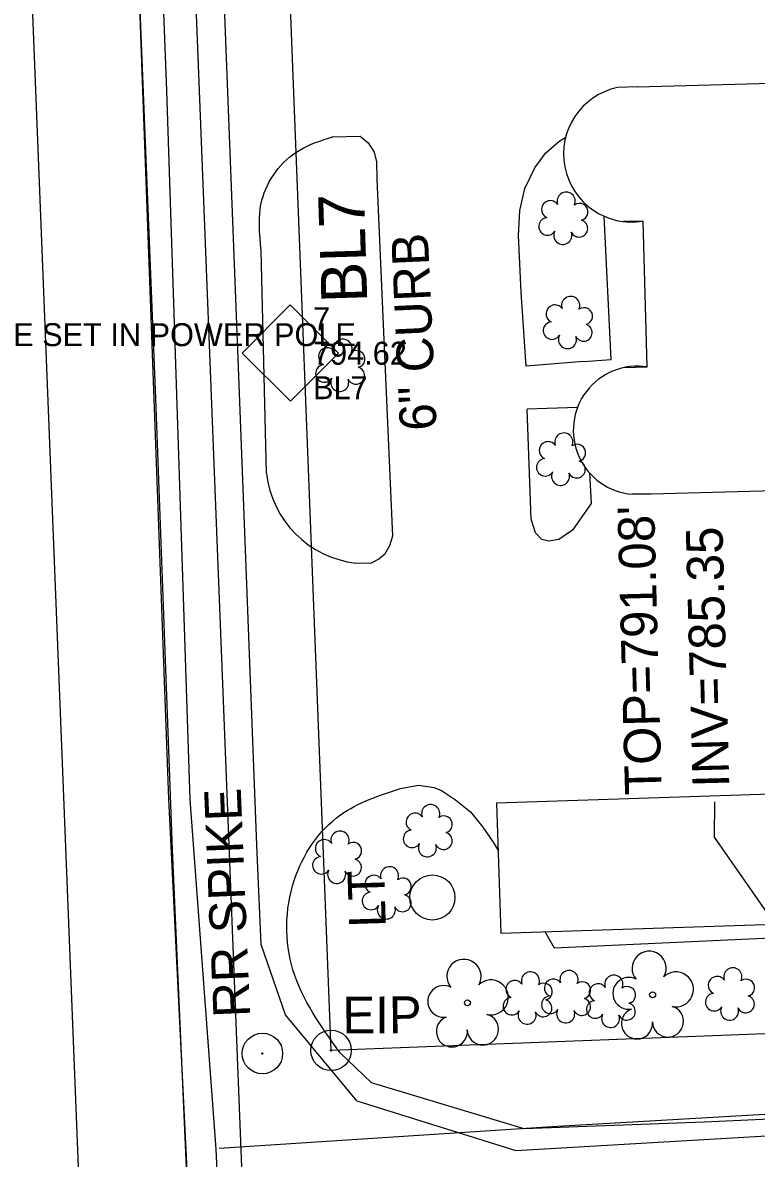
# Model space of a CAD drawing. Extents: x 1627482 to 1629573, y 760826 to 766301.
# Drawn here: x 1628380.2 to 1628460.1, y 763876.2 to 763999.8 of the extents above; entities that cross this region are included whole.
import ezdxf

# ---------------------------------------------------------------- set-up
doc = ezdxf.new("R2010")
doc.units = 0
for name, color, linetype in [('CTL Secondary Horizontal and Vertical CELL', 7, 'Continuous'), ('CTL Secondary Horizontal and Vertical Cogo Comment', 7, 'Continuous'), ('CTL Secondary Horizontal and Vertical Cogo Elevation', 7, 'Continuous'), ('CTL Secondary Horizontal and Vertical Cogo Number', 7, 'Continuous'), ('CTL Secondary Horizontal and Vertical Text', 7, 'Continuous'), ('CTL Vertical Benchmark Cogo Comment', 7, 'Continuous'), ('Exist Building', 7, 'Continuous'), ('Exist Building Metal Canopy', 7, 'Continuous'), ('Exist Horizontal Alignment', 7, 'Continuous'), ('Exist Other Culture Area Outline', 7, 'Continuous'), ('Exist Property Iron Pin CELL', 7, 'Continuous'), ('Exist Property Iron Pin Text', 7, 'Continuous'), ('Exist Right of Way Line', 7, 'Continuous'), ('Exist Roads Curbs', 7, 'Continuous'), ('Exist Roads Curbs Text', 7, 'Continuous'), ('Exist Roads EOP', 7, 'Continuous'), ('Exist Roads EOT', 7, 'Continuous'), ('Exist Utilities Gas UG Line SUE LOS B', 7, 'Continuous'), ('Exist Utilities Other Pole CELL', 7, 'Continuous'), ('Exist Utilities Other Pole Text', 7, 'Continuous'), ('Exist Utilities Sanitary Sewer Manhole Text', 7, 'Continuous'), ('Exist Utilities Sanitary Sewer UG Line', 7, 'Continuous'), ('Exist Utilities Sanitary Sewer UG Line Invert Elevation', 7, 'Continuous'), ('Exist Utilities Sanitary Sewer UG Line Leader', 7, 'Continuous'), ('Exist Utilities Water UG Line SUE LOS B', 7, 'Continuous'), ('Exist Vegetation Shrub CELL', 7, 'Continuous'), ('Exist Vegetation Tree CELL', 7, 'Continuous')]:
    doc.layers.add(name, color=color, linetype=linetype)

# ---------------------------------------------------------------- blocks, each defined once
blk = doc.blocks.new('EXIST PROPERTY IRON PIN_368')
at = {"layer": 'Exist Property Iron Pin CELL'}
for radius in [3.36, 0.108]:
    blk.add_circle((0, 0), radius, dxfattribs=at)

msp = doc.modelspace()

# ---------------------------------------------------------------- linework, layer by layer
at = {"layer": 'CTL Secondary Horizontal and Vertical CELL'}
msp.add_line((1628409.34, 763963.83), (1628409.34, 763963.83), dxfattribs=at)
msp.add_lwpolyline([(1628404.13, 763963.85), (1628409.37, 763969.09), (1628414.62, 763963.84), (1628409.38, 763958.6)], close=True, dxfattribs=at)
at = {"layer": 'Exist Building'}
for p, q in [((1628447.21, 763992.84), (1628445, 763992.75)), ((1628448.23, 763962.34), (1628447.8, 763978.22)), ((1628441.31, 763962.93), (1628435.07, 763962.43)), ((1628440.66, 763957.94), (1628435.17, 763957.75))]:
    msp.add_line(p, q, dxfattribs=at)
for points in [[(1628447.19, 763992.84), (1628447.21, 763992.84), (1628492.18, 763994.07), (1628492.4, 763985.86), (1628538.86, 763987.12), (1628539.46, 763965.07), (1628527.45, 763964.75), (1628527.83, 763950.63), (1628448.67, 763948.48), (1628446.6, 763948.49)], [(1628447.8, 763978.22), (1628445.68, 763978.17)], [(1628445.76, 763962.27), (1628448.23, 763962.34)]]:
    msp.add_lwpolyline(points, dxfattribs=at)
for centre, radius, start, end in [((1628446.54, 763985.51), 7.4, 102.04, 279.7685), ((1628447.18, 763955.44), 6.98, 81.3515, 265.2404)]:
    msp.add_arc(centre, radius, start, end, dxfattribs=at)
at = {"layer": 'Exist Building Metal Canopy'}
msp.add_lwpolyline([(1628555.82, 763918.91), (1628431.84, 763914.86), (1628432.31, 763900.72), (1628556.29, 763904.77)], close=True, dxfattribs=at)
at = {"layer": 'Exist Horizontal Alignment'}
msp.add_line((1628461.18, 761975.88), (1628351.56, 764755.6), dxfattribs=at)
at = {"layer": 'Exist Other Culture Area Outline'}
msp.add_lwpolyline([(1628441.31, 763962.93), (1628444.32, 763963.14), (1628443.57, 763978.74)], dxfattribs=at)
at = {"layer": 'Exist Right of Way Line'}
msp.add_lwpolyline([(1628629.23, 763896.22), (1628413.81, 763887.95), (1628407.97, 764037.8)], dxfattribs=at)
at = {"layer": 'Exist Roads Curbs'}
for p, q in [((1628414.01, 763987.37), (1628413.96, 763987.4)), ((1628406.78, 763950.74), (1628406.2, 763975.01)), ((1628416.5, 763940.98), (1628416.51, 763940.98)), ((1628421.35, 763916.45), (1628421.38, 763916.44)), ((1628431.48, 763910.62), (1628432.01, 763909.69)), ((1628437.08, 763900.88), (1628438.1, 763899.1)), ((1628414.79, 763887.7), (1628414.79, 763887.7))]:
    msp.add_line(p, q, dxfattribs=at)
for points in [[(1628414.01, 763987.37), (1628416.98, 763987.46), (1628417.84, 763986.72), (1628418.51, 763985.7), (1628418.77, 763984.66), (1628418.78, 763982.76), (1628419.57, 763965.3), (1628420.5, 763943.92), (1628420.19, 763942.88), (1628419.62, 763941.94), (1628419, 763941.4), (1628418.1, 763940.94), (1628416.51, 763940.98)], [(1628435.07, 763962.43), (1628434.51, 763970.46), (1628434.24, 763976.66), (1628434.37, 763979.35), (1628434.91, 763981.76), (1628435.99, 763984), (1628437.16, 763985.61), (1628438.64, 763986.88), (1628439.38, 763987.36)], [(1628441.96, 763950.81), (1628442.16, 763947.49), (1628440.12, 763944.57), (1628438.63, 763943.56), (1628437.53, 763943.37), (1628436.77, 763943.55), (1628436.08, 763944.27), (1628435.6, 763945.77), (1628435.17, 763957.75)], [(1628421.38, 763916.44), (1628423.33, 763916.81), (1628425.03, 763916.57), (1628425.83, 763916.24), (1628427.36, 763915.21), (1628429, 763913.93), (1628430.34, 763912.24), (1628431.48, 763910.62)], [(1628438.1, 763899.1), (1628498.67, 763901.9), (1628545.14, 763903.55)], [(1628552.59, 763884.54), (1628527.87, 763883.37), (1628490.27, 763881.77), (1628454.44, 763880.15), (1628434.85, 763879.42), (1628418.21, 763884.4), (1628414.79, 763887.7)]]:
    msp.add_lwpolyline(points, dxfattribs=at)
msp.add_ellipse((1628417.74, 763951.95), major_axis=(6.43, -8.97), ratio=0.998624, start_param=4.200206, end_param=5.548948, dxfattribs=at)
for points in [[(1628406.2, 763975.01), (1628406.28, 763980.49), (1628410.33, 763985.91), (1628414.01, 763987.37)], [(1628414.79, 763887.7), (1628409.66, 763896.72), (1628409.79, 763906.45), (1628414.84, 763913.58), (1628421.35, 763916.45)]]:
    msp.add_spline(points, degree=3, dxfattribs=at)
at = {"layer": 'Exist Roads EOP'}
for q in [(1628408.84, 763891.81), (1628433.94, 763877.05)]:
    msp.add_line((1628416.6, 763882.46), q, dxfattribs=at)
for points in [[(1628408.84, 763891.81), (1628406.21, 763899.46), (1628405.73, 763910.27), (1628403.83, 763959.47), (1628401.88, 764010.06), (1628400.01, 764060.11), (1628398.02, 764110.14), (1628396.15, 764159.43), (1628394.21, 764209.26), (1628392.32, 764258.48), (1628390.36, 764308.46), (1628388.47, 764357.87), (1628386.62, 764407.25), (1628384.64, 764457.21), (1628382.85, 764505.87)], [(1628416.6, 763882.46), (1628433.94, 763877.05), (1628552.51, 763883.97)]]:
    msp.add_lwpolyline(points, dxfattribs=at)
at = {"layer": 'Exist Roads EOT'}
msp.add_lwpolyline([(1628372.75, 764529.41), (1628373.69, 764505.24), (1628375.41, 764455.77), (1628377.18, 764406.72), (1628379.24, 764357.37), (1628381.34, 764307.42), (1628382.92, 764258.08), (1628384.96, 764208.76), (1628386.88, 764159.37), (1628389.04, 764109.02), (1628390.75, 764059.72), (1628392.64, 764009.33), (1628394.69, 763958.92), (1628396.48, 763909.8), (1628398.7, 763859.53)], dxfattribs=at)
at = {"layer": 'Exist Utilities Gas UG Line SUE LOS B'}
for points in [[(1628413.99, 763549.83), (1628410.61, 763659.76), (1628406.72, 763757.73), (1628401.3, 763877.18), (1628398.45, 763915.27), (1628395.93, 763992.39), (1628393.09, 764066.3), (1628389.92, 764168.16), (1628388.3, 764264.41), (1628388.86, 764316.24), (1628388.66, 764366.29), (1628385.61, 764456.2), (1628379.32, 764518.2), (1628376.01, 764570.05), (1628373.69, 764583.54), (1628373.66, 764583.52), (1628369.04, 764671.92), (1628368.81, 764733.47), (1628365.47, 764801.3), (1628365.41, 764842.67), (1628323.45, 764841.73)], [(1628401.62, 763877.31), (1628437.85, 763879.67), (1628499.31, 763883.23), (1628538.09, 763884.2), (1628595.67, 763885.75)]]:
    msp.add_lwpolyline(points, dxfattribs=at)
at = {"layer": 'Exist Utilities Other Pole CELL'}
msp.add_circle((1628424.85, 763904.59), 2.46, dxfattribs=at)
at = {"layer": 'Exist Utilities Sanitary Sewer UG Line'}
msp.add_line((1628404.33, 763869.48), (1628385.46, 764348.07), dxfattribs=at)
at = {"layer": 'Exist Utilities Sanitary Sewer UG Line Leader'}
msp.add_lwpolyline([(1628483.37, 763871.36), (1628455.59, 763911.15), (1628455.61, 763915.02)], dxfattribs=at)
at = {"layer": 'Exist Utilities Water UG Line SUE LOS B'}
msp.add_lwpolyline([(1628407.24, 763655.16), (1628402.4, 763754.94), (1628399.06, 763856.51), (1628396.12, 763915.33), (1628393.3, 763992.46), (1628390.7, 764066.34), (1628386.72, 764168.39), (1628382.56, 764256.29), (1628378.23, 764373.67), (1628375.54, 764455.63), (1628372.03, 764542.25), (1628370.17, 764583.36), (1628366.9, 764671.42), (1628365.27, 764739.23), (1628362.16, 764808.05), (1628361.5, 764823.25), (1628356.13, 764896.21), (1628352.11, 764986.77), (1628341.94, 765081.92), (1628331.48, 765195.63), (1628321.82, 765290.23), (1628312.98, 765379.55), (1628303.79, 765478.36)], dxfattribs=at)
at = {"layer": 'Exist Vegetation Shrub CELL'}
for p, q in [((1628439.19, 763978.34), (1628439.19, 763978.34)), ((1628439.68, 763966.99), (1628439.68, 763966.99)), ((1628414.88, 763962.33), (1628414.88, 763962.33)), ((1628438.94, 763952.12), (1628438.94, 763952.12)), ((1628424.43, 763911.68), (1628424.43, 763911.68)), ((1628414.55, 763908.79), (1628414.55, 763908.79)), ((1628419.96, 763904.91), (1628419.96, 763904.91)), ((1628435.3, 763893.47), (1628435.3, 763893.47)), ((1628439.5, 763893.62), (1628439.5, 763893.62)), ((1628444.39, 763893.11), (1628444.39, 763893.11)), ((1628457.36, 763893.91), (1628457.36, 763893.91))]:
    msp.add_line(p, q, dxfattribs=at)
for centre, radius, start, end in [((1628439.42, 763980.38), 0.99, 334.8391, 200.4717), ((1628437.71, 763979.47), 0.968, 35.8908, 245.4216), ((1628440.86, 763979.21), 0.929, 284.4567, 126.0861), ((1628437.39, 763977.63), 0.955, 95.1099, 327.9534), ((1628440.83, 763977.41), 0.937, 204.9913, 73.4601), ((1628439.06, 763976.65), 0.984, 151.2797, 21.387), ((1628439.91, 763969.03), 0.99, 334.8391, 200.4717), ((1628438.2, 763968.12), 0.968, 35.8908, 245.4216), ((1628441.36, 763967.86), 0.929, 284.4567, 126.0861), ((1628437.88, 763966.29), 0.955, 95.1099, 327.9534), ((1628441.32, 763966.07), 0.937, 204.9913, 73.4601), ((1628415.11, 763964.37), 0.99, 334.8391, 200.4717), ((1628439.56, 763965.31), 0.984, 151.2797, 21.387), ((1628413.4, 763963.46), 0.968, 35.8908, 245.4216), ((1628416.56, 763963.2), 0.929, 284.4567, 126.0861), ((1628413.08, 763961.63), 0.955, 95.1099, 327.9534), ((1628416.52, 763961.4), 0.937, 204.9913, 73.4601), ((1628414.75, 763960.65), 0.984, 151.2797, 21.387), ((1628439.17, 763954.16), 0.99, 334.8391, 200.4717), ((1628437.45, 763953.24), 0.968, 35.8908, 245.4216), ((1628440.61, 763952.99), 0.929, 284.4567, 126.0861), ((1628437.14, 763951.41), 0.955, 95.1099, 327.9534), ((1628440.57, 763951.19), 0.937, 204.9913, 73.4601), ((1628438.81, 763950.43), 0.984, 151.2797, 21.387), ((1628424.66, 763913.72), 0.99, 334.8391, 200.4717), ((1628422.95, 763912.81), 0.968, 35.8908, 245.4216), ((1628426.1, 763912.55), 0.929, 284.4567, 126.0861), ((1628414.78, 763910.83), 0.99, 334.8391, 200.4717), ((1628422.63, 763910.97), 0.955, 95.1099, 327.9534), ((1628426.07, 763910.75), 0.937, 204.9913, 73.4601), ((1628413.06, 763909.92), 0.968, 35.8908, 245.4216), ((1628416.22, 763909.66), 0.929, 284.4567, 126.0861), ((1628424.3, 763910), 0.984, 151.2797, 21.387), ((1628412.75, 763908.09), 0.955, 95.1099, 327.9534), ((1628416.18, 763907.86), 0.937, 204.9913, 73.4601), ((1628420.18, 763906.95), 0.99, 334.8391, 200.4717), ((1628414.42, 763907.11), 0.984, 151.2797, 21.387), ((1628418.47, 763906.04), 0.968, 35.8908, 245.4216), ((1628421.63, 763905.78), 0.929, 284.4567, 126.0861), ((1628418.15, 763904.21), 0.955, 95.1099, 327.9534), ((1628421.59, 763903.98), 0.937, 204.9913, 73.4601), ((1628419.83, 763903.23), 0.984, 151.2797, 21.387), ((1628457.58, 763895.95), 0.99, 334.8391, 200.4717), ((1628433.81, 763894.59), 0.968, 35.8908, 245.4216), ((1628435.53, 763895.51), 0.99, 334.8391, 200.4717), ((1628438.02, 763894.75), 0.968, 35.8908, 245.4216), ((1628439.73, 763895.66), 0.99, 334.8391, 200.4717), ((1628444.61, 763895.15), 0.99, 334.8391, 200.4717), ((1628455.87, 763895.03), 0.968, 35.8908, 245.4216), ((1628459.03, 763894.77), 0.929, 284.4567, 126.0861), ((1628436.97, 763894.34), 0.929, 284.4567, 126.0861), ((1628441.17, 763894.49), 0.929, 284.4567, 126.0861), ((1628442.9, 763894.23), 0.968, 35.8908, 245.4216), ((1628446.06, 763893.98), 0.929, 284.4567, 126.0861), ((1628433.5, 763892.76), 0.955, 95.1099, 327.9534), ((1628436.93, 763892.54), 0.937, 204.9913, 73.4601), ((1628437.7, 763892.91), 0.955, 95.1099, 327.9534), ((1628441.14, 763892.69), 0.937, 204.9913, 73.4601), ((1628442.59, 763892.4), 0.955, 95.1099, 327.9534), ((1628446.02, 763892.18), 0.937, 204.9913, 73.4601), ((1628455.55, 763893.2), 0.955, 95.1099, 327.9534), ((1628458.99, 763892.98), 0.937, 204.9913, 73.4601), ((1628435.17, 763891.78), 0.984, 151.2797, 21.387), ((1628439.37, 763891.93), 0.984, 151.2797, 21.387), ((1628444.26, 763891.42), 0.984, 151.2797, 21.387), ((1628457.23, 763892.22), 0.984, 151.2797, 21.387)]:
    msp.add_arc(centre, radius, start, end, dxfattribs=at)
at = {"layer": 'Exist Vegetation Tree CELL'}
for p, q in [((1628428.67, 763893.13), (1628428.67, 763893.13)), ((1628448.84, 763894), (1628448.84, 763894))]:
    msp.add_line(p, q, dxfattribs=at)
for centre in [(1628448.84, 763894), (1628428.67, 763893.13)]:
    msp.add_circle(centre, 0.326, dxfattribs=at)
for centre, radius, start, end in [((1628448.46, 763896.88), 1.86, 330.1651, 219.7134), ((1628428.29, 763896), 1.86, 330.1651, 219.7134), ((1628431.22, 763893.72), 1.9, 257.1011, 134.1999), ((1628446.24, 763894.16), 1.73, 62.6636, 279.3457), ((1628451.39, 763894.59), 1.9, 257.1011, 134.1999), ((1628426.07, 763893.28), 1.73, 62.6636, 279.3457), ((1628430.35, 763890.23), 1.7, 181.2822, 74.56), ((1628447.14, 763890.88), 1.69, 111.5671, 6.231), ((1628450.51, 763891.1), 1.7, 181.2822, 74.56), ((1628426.97, 763890.01), 1.69, 111.5671, 6.231)]:
    msp.add_arc(centre, radius, start, end, dxfattribs=at)

# ---------------------------------------------------------------- block references
at = {"layer": 'Exist Property Iron Pin CELL', "xscale": 0.6561666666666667, "yscale": 0.6561666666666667}
for p in [(1628406.33, 763887.61), (1628413.81, 763887.95)]:
    msp.add_blockref('EXIST PROPERTY IRON PIN_368', p, dxfattribs=at)

# ---------------------------------------------------------------- texts
at = {"layer": 'CTL Secondary Horizontal and Vertical Cogo Comment'}
msp.add_text('BL7', height=2.5, dxfattribs=at).set_placement((1628411.84, 763958.83))
at = {"layer": 'CTL Secondary Horizontal and Vertical Cogo Elevation'}
msp.add_text('794.62', height=2.5, dxfattribs=at).set_placement((1628411.84, 763962.58))
at = {"layer": 'CTL Secondary Horizontal and Vertical Cogo Number'}
msp.add_text('7', height=2.5, dxfattribs=at).set_placement((1628411.84, 763966.33))
at = {"layer": 'CTL Secondary Horizontal and Vertical Text'}
msp.add_text('BL7', height=5, rotation=91.7713, dxfattribs=at).set_placement((1628417.76, 763969.38))
at = {"layer": 'CTL Vertical Benchmark Cogo Comment'}
msp.add_text('BENCHTIE SET IN POWER POLE', height=2.5, dxfattribs=at).set_placement((1628364.5, 763964.6))
at = {"layer": 'Exist Property Iron Pin Text'}
for s, rotation, p in [('RR SPIKE', 92.3749, (1628405, 763891.61)), ('EIP', 0.3159, (1628415.06, 763889.79))]:
    msp.add_text(s, height=4, rotation=rotation, dxfattribs=at).set_placement(p)
at = {"layer": 'Exist Roads Curbs Text'}
msp.add_text('6" CURB', height=4, rotation=92.5946, dxfattribs=at).set_placement((1628425.32, 763955.49))
at = {"layer": 'Exist Utilities Other Pole Text'}
msp.add_text('LT', height=4, rotation=91.7713, dxfattribs=at).set_placement((1628419.78, 763901.38))
at = {"layer": 'Exist Utilities Sanitary Sewer Manhole Text'}
msp.add_text("TOP=791.08'", height=4, rotation=91.5197, dxfattribs=at).set_placement((1628449.84, 763915.81))
at = {"layer": 'Exist Utilities Sanitary Sewer UG Line Invert Elevation'}
msp.add_text('INV=785.35', height=4, rotation=91.5197, dxfattribs=at).set_placement((1628457.2, 763916.61))

doc.saveas('drawing.dxf')
